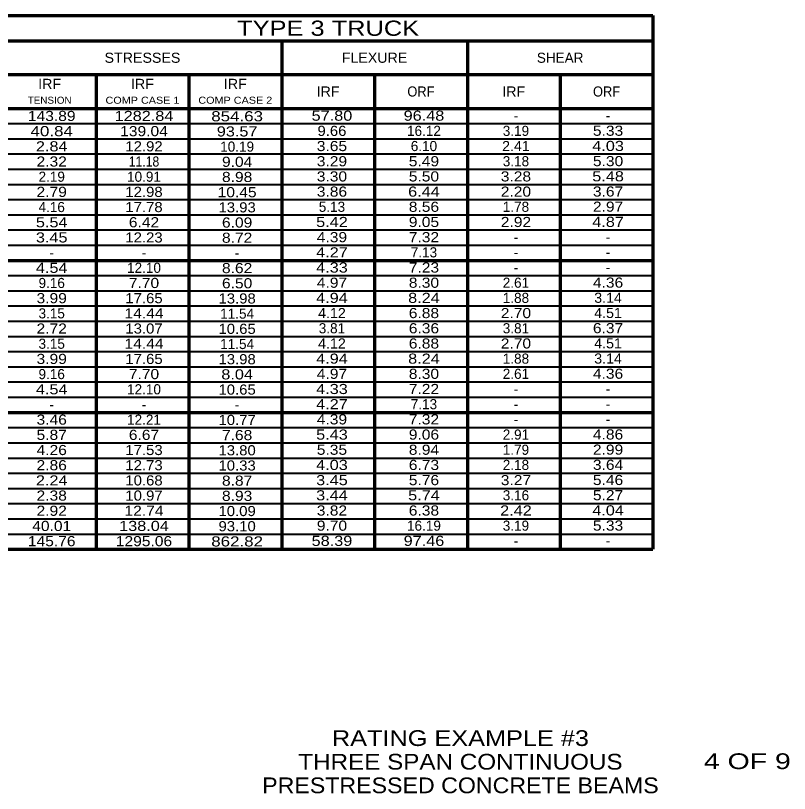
# Model space of a CAD drawing. Extents: x -1807 to -1668, y -81 to 6.
# Drawn here: x -1713.57 to -1667.71, y -81.25 to -35.15 of the extents above; entities that cross this region are included whole.
import ezdxf
from ezdxf.enums import TextEntityAlignment as Align

# ---------------------------------------------------------------- set-up
doc = ezdxf.new("R2010")
doc.units = 0
doc.header["$LTSCALE"] = 0.24
doc.layers.add('1', color=7, linetype='Continuous', lineweight=70)
doc.layers.add('5', color=7, linetype='Continuous', lineweight=40)
doc.layers.add('21', color=7, linetype='Continuous')
doc.layers.add('9', color=7, linetype='Continuous')

msp = doc.modelspace()

# ---------------------------------------------------------------- linework, layer by layer
at = {"layer": '1'}
for p, q in [((-1761.797, -35.1469), (-1675.797, -35.1469)), ((-1675.797, -35.1469), (-1675.797, -66.7771)), ((-1761.797, -36.6469), (-1675.797, -36.6469)), ((-1697.797, -36.6469), (-1697.797, -66.7771)), ((-1686.797, -36.6469), (-1686.797, -66.7771)), ((-1752.797, -38.6469), (-1675.797, -38.6469)), ((-1708.797, -38.6469), (-1708.797, -66.7771)), ((-1703.297, -38.6469), (-1703.297, -66.7771)), ((-1692.297, -38.6469), (-1692.297, -66.7771)), ((-1681.297, -38.6469), (-1681.297, -66.7771)), ((-1761.797, -40.6469), (-1675.797, -40.6469)), ((-1761.797, -49.6573), (-1675.797, -49.6573)), ((-1761.797, -58.6677), (-1675.797, -58.6677)), ((-1761.797, -66.7771), (-1675.797, -66.7771))]:
    msp.add_line(p, q, dxfattribs=at)
at = {"layer": '5'}
for p, q in [((-1757.797, -41.5479), (-1675.797, -41.5479)), ((-1757.797, -42.449), (-1675.797, -42.449)), ((-1757.797, -43.35), (-1675.797, -43.35)), ((-1757.797, -44.2511), (-1675.797, -44.2511)), ((-1757.797, -45.1521), (-1675.797, -45.1521)), ((-1757.797, -46.0532), (-1675.797, -46.0532)), ((-1757.797, -46.9542), (-1675.797, -46.9542)), ((-1757.797, -47.8552), (-1675.797, -47.8552)), ((-1757.797, -48.7563), (-1675.797, -48.7563)), ((-1757.797, -50.5583), (-1675.797, -50.5583)), ((-1757.797, -51.4594), (-1675.797, -51.4594)), ((-1757.797, -52.3604), (-1675.797, -52.3604)), ((-1757.797, -53.2615), (-1675.797, -53.2615)), ((-1757.797, -54.1625), (-1675.797, -54.1625)), ((-1757.797, -55.0636), (-1675.797, -55.0636)), ((-1757.797, -55.9646), (-1675.797, -55.9646)), ((-1757.797, -56.8657), (-1675.797, -56.8657)), ((-1757.797, -57.7667), (-1675.797, -57.7667)), ((-1757.797, -59.5688), (-1675.797, -59.5688)), ((-1757.797, -60.4698), (-1675.797, -60.4698)), ((-1757.797, -61.3708), (-1675.797, -61.3708)), ((-1757.797, -62.2719), (-1675.797, -62.2719)), ((-1757.797, -63.1729), (-1675.797, -63.1729)), ((-1757.797, -64.074), (-1675.797, -64.074)), ((-1757.797, -64.975), (-1675.797, -64.975)), ((-1757.797, -65.8761), (-1675.797, -65.8761))]:
    msp.add_line(p, q, dxfattribs=at)

# ---------------------------------------------------------------- texts
at = {"layer": '21'}
for s, height, width, p in [('STRESSES', 0.6, 1.05, (-1706.0468, -37.9469)), ('FLEXURE', 0.6, 1.05, (-1692.2967, -37.9469)), ('IRF', 0.6, 1.05, (-1711.5467, -39.4969)), ('IRF', 0.6, 1.05, (-1706.0467, -39.4969)), ('IRF', 0.6, 1.05, (-1700.5467, -39.4969)), ('IRF', 0.6, 1.05, (-1695.0467, -39.9469)), ('ORF', 0.6, 0.95, (-1689.5468, -39.9469)), ('IRF', 0.6, 1.05, (-1684.0467, -39.9469)), ('ORF', 0.6, 0.95, (-1678.5468, -39.9469)), ('TENSION', 0.4167, 1.05, (-1711.5468, -40.3742)), ('COMP CASE 1', 0.4167, 1.15, (-1706.0469, -40.3742)), ('COMP CASE 2', 0.4167, 1.15, (-1700.5469, -40.3742)), ('RATING EXAMPLE #3', 0.9333, 1.2, (-1687.2057, -78.4392)), ('THREE SPAN CONTINUOUS', 0.9333, 1.15, (-1687.2057, -79.8392)), ('4 OF 9', 0.9333, 1.35, (-1670.2065, -79.8089)), ('PRESTRESSED CONCRETE BEAMS', 0.9333, 1.1, (-1687.2056, -81.2392))]:
    msp.add_text(s, height=height, dxfattribs=dict(at, width=width)).set_placement(p, align=Align.CENTER)
msp.add_text('SHEAR', height=0.6, dxfattribs=at).set_placement((-1681.2968, -37.9469), align=Align.CENTER)
at = {"layer": '9'}
for s, height, width, p in [('TYPE 3 TRUCK', 0.9, 1.25, (-1695.0465, -36.3469)), ('143.89', 0.6, 1.15, (-1711.4237, -41.3973)), ('1282.84', 0.6, 1.2, (-1705.9557, -41.3973)), ('854.63', 0.6, 1.25, (-1700.4374, -41.414)), ('57.80', 0.6, 1.2, (-1694.8189, -41.3806)), ('96.48', 0.6, 1.2, (-1689.3676, -41.3806)), ('40.84', 0.6, 1.25, (-1711.4237, -42.2973)), ('139.04', 0.6, 1.15, (-1705.9557, -42.2973)), ('93.57', 0.6, 1.2, (-1700.4374, -42.314)), ('9.66', 0.6, 1.1, (-1694.8189, -42.2806)), ('5.33', 0.6, 1.15, (-1678.4582, -42.2732)), ('2.84', 0.6, 1.2, (-1711.4237, -43.1973)), ('12.92', 0.6, 1.1, (-1705.9557, -43.1973)), ('3.65', 0.6, 1.15, (-1694.8189, -43.1806)), ('2.41', 0.6, 1.05, (-1683.9164, -43.1806)), ('4.03', 0.6, 1.2, (-1678.4582, -43.1732)), ('2.32', 0.6, 1.15, (-1711.4237, -44.0973)), ('11.18', 0.6, 0.9, (-1705.9556, -44.0973)), ('9.04', 0.6, 1.15, (-1700.4375, -44.114)), ('3.29', 0.6, 1.15, (-1694.819, -44.0806)), ('5.49', 0.6, 1.15, (-1689.3676, -44.0806)), ('5.30', 0.6, 1.15, (-1678.4582, -44.0733)), ('8.98', 0.6, 1.15, (-1700.4374, -45.014)), ('3.30', 0.6, 1.15, (-1694.8189, -44.9806)), ('5.50', 0.6, 1.15, (-1689.3676, -44.9806)), ('3.28', 0.6, 1.15, (-1683.9164, -44.9806)), ('5.48', 0.6, 1.2, (-1678.4582, -44.9733)), ('2.79', 0.6, 1.15, (-1711.4237, -45.8973)), ('12.98', 0.6, 1.1, (-1705.9557, -45.8973)), ('10.45', 0.6, 1.15, (-1700.4374, -45.914)), ('3.86', 0.6, 1.15, (-1694.819, -45.8806)), ('6.44', 0.6, 1.2, (-1689.3676, -45.8806)), ('2.20', 0.6, 1.15, (-1683.9163, -45.8806)), ('3.67', 0.6, 1.15, (-1678.4582, -45.8732)), ('17.78', 0.6, 1.1, (-1705.9557, -46.7973)), ('13.93', 0.6, 1.1, (-1700.4374, -46.814)), ('8.56', 0.6, 1.15, (-1689.3676, -46.7806)), ('2.97', 0.6, 1.15, (-1678.4582, -46.7732)), ('5.54', 0.6, 1.2, (-1711.4237, -47.6973)), ('6.42', 0.6, 1.15, (-1705.9557, -47.6973)), ('6.09', 0.6, 1.15, (-1700.4374, -47.714)), ('5.42', 0.6, 1.2, (-1694.8189, -47.6806)), ('9.05', 0.6, 1.15, (-1689.3676, -47.6806)), ('2.92', 0.6, 1.15, (-1683.9163, -47.6806)), ('4.87', 0.6, 1.2, (-1678.4582, -47.6732)), ('3.45', 0.6, 1.2, (-1711.4237, -48.5973)), ('12.23', 0.6, 1.1, (-1705.9557, -48.5973)), ('8.72', 0.6, 1.15, (-1700.4375, -48.614)), ('4.39', 0.6, 1.15, (-1694.819, -48.5806)), ('7.32', 0.6, 1.15, (-1689.3676, -48.5806)), ('4.27', 0.6, 1.2, (-1694.8189, -49.4806)), ('4.33', 0.6, 1.2, (-1694.8189, -50.3806)), ('7.23', 0.6, 1.15, (-1689.3676, -50.3806)), ('4.54', 0.6, 1.2, (-1711.4237, -50.3973)), ('8.62', 0.6, 1.15, (-1700.4374, -50.414)), ('7.70', 0.6, 1.15, (-1705.9557, -51.2973)), ('6.50', 0.6, 1.15, (-1700.4375, -51.314)), ('4.97', 0.6, 1.15, (-1694.8189, -51.2806)), ('8.30', 0.6, 1.15, (-1689.3676, -51.2806)), ('4.36', 0.6, 1.15, (-1678.4582, -51.2732)), ('3.99', 0.6, 1.15, (-1711.4237, -52.1973)), ('17.65', 0.6, 1.1, (-1705.9556, -52.1973)), ('13.98', 0.6, 1.1, (-1700.4374, -52.214)), ('4.94', 0.6, 1.2, (-1694.8189, -52.1806)), ('8.24', 0.6, 1.2, (-1689.3676, -52.1806)), ('3.14', 0.6, 1.05, (-1678.4582, -52.1732)), ('14.44', 0.6, 1.15, (-1705.9557, -53.0973)), ('4.12', 0.6, 1.05, (-1694.8189, -53.0806)), ('6.88', 0.6, 1.15, (-1689.3676, -53.0806)), ('2.70', 0.6, 1.15, (-1683.9163, -53.0806)), ('4.51', 0.6, 1.05, (-1678.4582, -53.0733)), ('2.72', 0.6, 1.15, (-1711.4237, -53.9973)), ('13.07', 0.6, 1.1, (-1705.9556, -53.9973)), ('10.65', 0.6, 1.1, (-1700.4374, -54.014)), ('6.36', 0.6, 1.15, (-1689.3676, -53.9806)), ('6.37', 0.6, 1.15, (-1678.4582, -53.9733)), ('14.44', 0.6, 1.15, (-1705.9557, -54.8973)), ('4.12', 0.6, 1.05, (-1694.8189, -54.8806)), ('6.88', 0.6, 1.15, (-1689.3676, -54.8806)), ('2.70', 0.6, 1.15, (-1683.9163, -54.8806)), ('4.51', 0.6, 1.05, (-1678.4582, -54.8732)), ('3.99', 0.6, 1.15, (-1711.4237, -55.7973)), ('17.65', 0.6, 1.1, (-1705.9556, -55.7973)), ('13.98', 0.6, 1.1, (-1700.4374, -55.814)), ('4.94', 0.6, 1.2, (-1694.8189, -55.7806)), ('8.24', 0.6, 1.2, (-1689.3676, -55.7806)), ('3.14', 0.6, 1.05, (-1678.4582, -55.7732)), ('7.70', 0.6, 1.15, (-1705.9557, -56.6973)), ('8.04', 0.6, 1.2, (-1700.4374, -56.714)), ('4.97', 0.6, 1.15, (-1694.8189, -56.6806)), ('8.30', 0.6, 1.15, (-1689.3676, -56.6806)), ('4.36', 0.6, 1.15, (-1678.4582, -56.6732)), ('4.54', 0.6, 1.2, (-1711.4237, -57.5973)), ('10.65', 0.6, 1.1, (-1700.4374, -57.614)), ('4.33', 0.6, 1.2, (-1694.8189, -57.5806)), ('7.22', 0.6, 1.15, (-1689.3676, -57.5806)), ('4.27', 0.6, 1.2, (-1694.8189, -58.4806)), ('3.46', 0.6, 1.15, (-1711.4237, -59.3973)), ('10.77', 0.6, 1.1, (-1700.4375, -59.414)), ('4.39', 0.6, 1.15, (-1694.819, -59.3806)), ('7.32', 0.6, 1.15, (-1689.3676, -59.3806)), ('5.87', 0.6, 1.15, (-1711.4237, -60.2973)), ('6.67', 0.6, 1.15, (-1705.9557, -60.2973)), ('7.68', 0.6, 1.15, (-1700.4374, -60.314)), ('5.43', 0.6, 1.2, (-1694.8189, -60.2806)), ('9.06', 0.6, 1.15, (-1689.3675, -60.2806)), ('4.86', 0.6, 1.15, (-1678.4582, -60.2732)), ('4.26', 0.6, 1.15, (-1711.4237, -61.1973)), ('17.53', 0.6, 1.1, (-1705.9557, -61.1973)), ('13.80', 0.6, 1.1, (-1700.4374, -61.214)), ('5.35', 0.6, 1.15, (-1694.819, -61.1806)), ('8.94', 0.6, 1.15, (-1689.3676, -61.1806)), ('2.99', 0.6, 1.15, (-1678.4582, -61.1732)), ('2.86', 0.6, 1.15, (-1711.4237, -62.0973)), ('12.73', 0.6, 1.1, (-1705.9557, -62.0973)), ('10.33', 0.6, 1.1, (-1700.4374, -62.114)), ('4.03', 0.6, 1.2, (-1694.8189, -62.0806)), ('6.73', 0.6, 1.15, (-1689.3676, -62.0806)), ('3.64', 0.6, 1.15, (-1678.4582, -62.0732)), ('2.24', 0.6, 1.2, (-1711.4237, -62.9973)), ('10.68', 0.6, 1.1, (-1705.9557, -62.9973)), ('8.87', 0.6, 1.15, (-1700.4375, -63.014)), ('3.45', 0.6, 1.2, (-1694.8189, -62.9806)), ('5.76', 0.6, 1.15, (-1689.3676, -62.9806)), ('3.27', 0.6, 1.15, (-1683.9164, -62.9806)), ('5.46', 0.6, 1.15, (-1678.4582, -62.9733)), ('2.38', 0.6, 1.15, (-1711.4237, -63.8973)), ('10.97', 0.6, 1.1, (-1705.9557, -63.8973)), ('8.93', 0.6, 1.15, (-1700.4374, -63.914)), ('3.44', 0.6, 1.2, (-1694.8189, -63.8806)), ('5.74', 0.6, 1.2, (-1689.3676, -63.8806)), ('5.27', 0.6, 1.15, (-1678.4582, -63.8732)), ('2.92', 0.6, 1.15, (-1711.4237, -64.7973)), ('12.74', 0.6, 1.15, (-1705.9557, -64.7973)), ('10.09', 0.6, 1.1, (-1700.4375, -64.814)), ('3.82', 0.6, 1.15, (-1694.819, -64.7806)), ('6.38', 0.6, 1.15, (-1689.3676, -64.7806)), ('2.42', 0.6, 1.2, (-1683.9164, -64.7806)), ('4.04', 0.6, 1.2, (-1678.4582, -64.7733)), ('40.01', 0.6, 1.15, (-1711.4237, -65.6973)), ('138.04', 0.6, 1.2, (-1705.9556, -65.6973)), ('93.10', 0.6, 1.1, (-1700.4374, -65.714)), ('9.70', 0.6, 1.15, (-1694.8189, -65.6806)), ('5.33', 0.6, 1.15, (-1678.4582, -65.6732)), ('145.76', 0.6, 1.15, (-1711.4237, -66.5973)), ('1295.06', 0.6, 1.15, (-1705.9557, -66.5973)), ('862.82', 0.6, 1.25, (-1700.4374, -66.614)), ('58.39', 0.6, 1.2, (-1694.819, -66.5806)), ('97.46', 0.6, 1.2, (-1689.3676, -66.5806))]:
    msp.add_text(s, height=height, dxfattribs=dict(at, width=width)).set_placement(p, align=Align.CENTER)
for s, p in [('-', (-1683.9164, -41.3806)), ('-', (-1678.4582, -41.3732)), ('16.12', (-1689.3676, -42.2806)), ('3.19', (-1683.9164, -42.2806)), ('10.19', (-1700.4374, -43.214)), ('6.10', (-1689.3676, -43.1806)), ('3.18', (-1683.9164, -44.0806)), ('2.19', (-1711.4237, -44.9973)), ('10.91', (-1705.9557, -44.9973)), ('4.16', (-1711.4237, -46.7973)), ('5.13', (-1694.8189, -46.7806)), ('1.78', (-1683.9163, -46.7806)), ('-', (-1683.9164, -48.5806)), ('-', (-1678.4582, -48.5733)), ('7.13', (-1689.3676, -49.4806)), ('-', (-1711.4237, -49.4973)), ('-', (-1705.9557, -49.4973)), ('-', (-1700.4374, -49.514)), ('-', (-1683.9164, -49.4806)), ('-', (-1678.4582, -49.4733)), ('12.10', (-1705.9557, -50.3973)), ('-', (-1683.9164, -50.3806)), ('-', (-1678.4582, -50.3732)), ('9.16', (-1711.4237, -51.2973)), ('2.61', (-1683.9163, -51.2806)), ('1.88', (-1683.9164, -52.1806)), ('3.15', (-1711.4237, -53.0973)), ('11.54', (-1700.4374, -53.114)), ('3.81', (-1694.8189, -53.9806)), ('3.81', (-1683.9164, -53.9806)), ('3.15', (-1711.4237, -54.8973)), ('11.54', (-1700.4374, -54.914)), ('1.88', (-1683.9164, -55.7806)), ('9.16', (-1711.4237, -56.6973)), ('2.61', (-1683.9163, -56.6806)), ('12.10', (-1705.9557, -57.5973)), ('-', (-1683.9164, -57.5806)), ('-', (-1678.4582, -57.5733)), ('7.13', (-1689.3676, -58.4806)), ('-', (-1711.4237, -58.4973)), ('-', (-1705.9557, -58.4973)), ('-', (-1700.4374, -58.514)), ('-', (-1683.9164, -58.4806)), ('-', (-1678.4582, -58.4733)), ('12.21', (-1705.9557, -59.3973)), ('-', (-1683.9164, -59.3806)), ('-', (-1678.4582, -59.3732)), ('2.91', (-1683.9163, -60.2806)), ('1.79', (-1683.9164, -61.1806)), ('2.18', (-1683.9164, -62.0806)), ('3.16', (-1683.9164, -63.8806)), ('16.19', (-1689.3676, -65.6806)), ('3.19', (-1683.9164, -65.6806)), ('-', (-1683.9164, -66.5806)), ('-', (-1678.4582, -66.5733))]:
    msp.add_text(s, height=0.6, dxfattribs=at).set_placement(p, align=Align.CENTER)

doc.saveas('drawing.dxf')
